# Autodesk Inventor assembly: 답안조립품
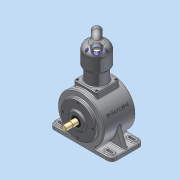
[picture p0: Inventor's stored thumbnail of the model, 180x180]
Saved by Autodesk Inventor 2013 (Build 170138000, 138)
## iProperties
Created: 2015-06
Part Number: 답안조립품
Document SubType Name: Assembly
Designer: Administrator
Author: Administrator
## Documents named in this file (15)
- C:\Users\Administrator\Desktop\450606V1007\답안조립품.iam
- C:\Users\Administrator\Desktop\450606V1007\본체.ipt
- C:\Users\Administrator\Desktop\450606V1007\M4x0.7.ipt
- C:\Users\Administrator\Desktop\450606V1007\M5x0.8.ipt
- C:\Users\Administrator\Desktop\450606V1007\메인 크랭크 축-구동부.ipt
- C:\Users\Administrator\Desktop\450606V1007\메인커버.ipt
- C:\Users\Administrator\Desktop\450606V1007\베어링 6204.ipt
- C:\Users\Administrator\Desktop\450606V1007\베어링 NA 4902.ipt
- C:\Users\Administrator\Desktop\450606V1007\실린더.ipt
- C:\Users\Administrator\Desktop\450606V1007\실린더헤드.ipt
- C:\Users\Administrator\Desktop\450606V1007\오일실.ipt
- C:\Users\Administrator\Desktop\450606V1007\커넥팅 로드.ipt
- C:\Users\Administrator\Desktop\450606V1007\크랭크 서브축.ipt
- C:\Users\Administrator\Desktop\450606V1007\피스톤 핀.ipt
- C:\Users\Administrator\Desktop\450606V1007\피스톤.ipt
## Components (14 placed, 4 different names)
1. 피스톤 핀:1 — 플러쉬:1, 플러쉬:2
2. 피스톤:1 — 플러쉬:2
3. M4x0.7:1 — 각도:2
4. M4x0.7:3
5. M4x0.7:4
6. M4x0.7:5
7. M4x0.7:2
8. M4x0.7:6 — 각도:1
9. M4x0.7:7
10. M4x0.7:8
11. M5x0.8:1 — 각도:3
12. M5x0.8:2
13. M5x0.8:3
14. M5x0.8:4
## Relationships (5: Angle 3, Flush 2)
- 각도:1 [Angle]: M4x0.7:6
- 각도:2 [Angle]: M4x0.7:1
- 플러쉬:1 [Flush]: 피스톤 핀:1
- 플러쉬:2 [Flush]: 피스톤 핀:1 ↔ 피스톤:1
- 각도:3 [Angle]: M5x0.8:1
